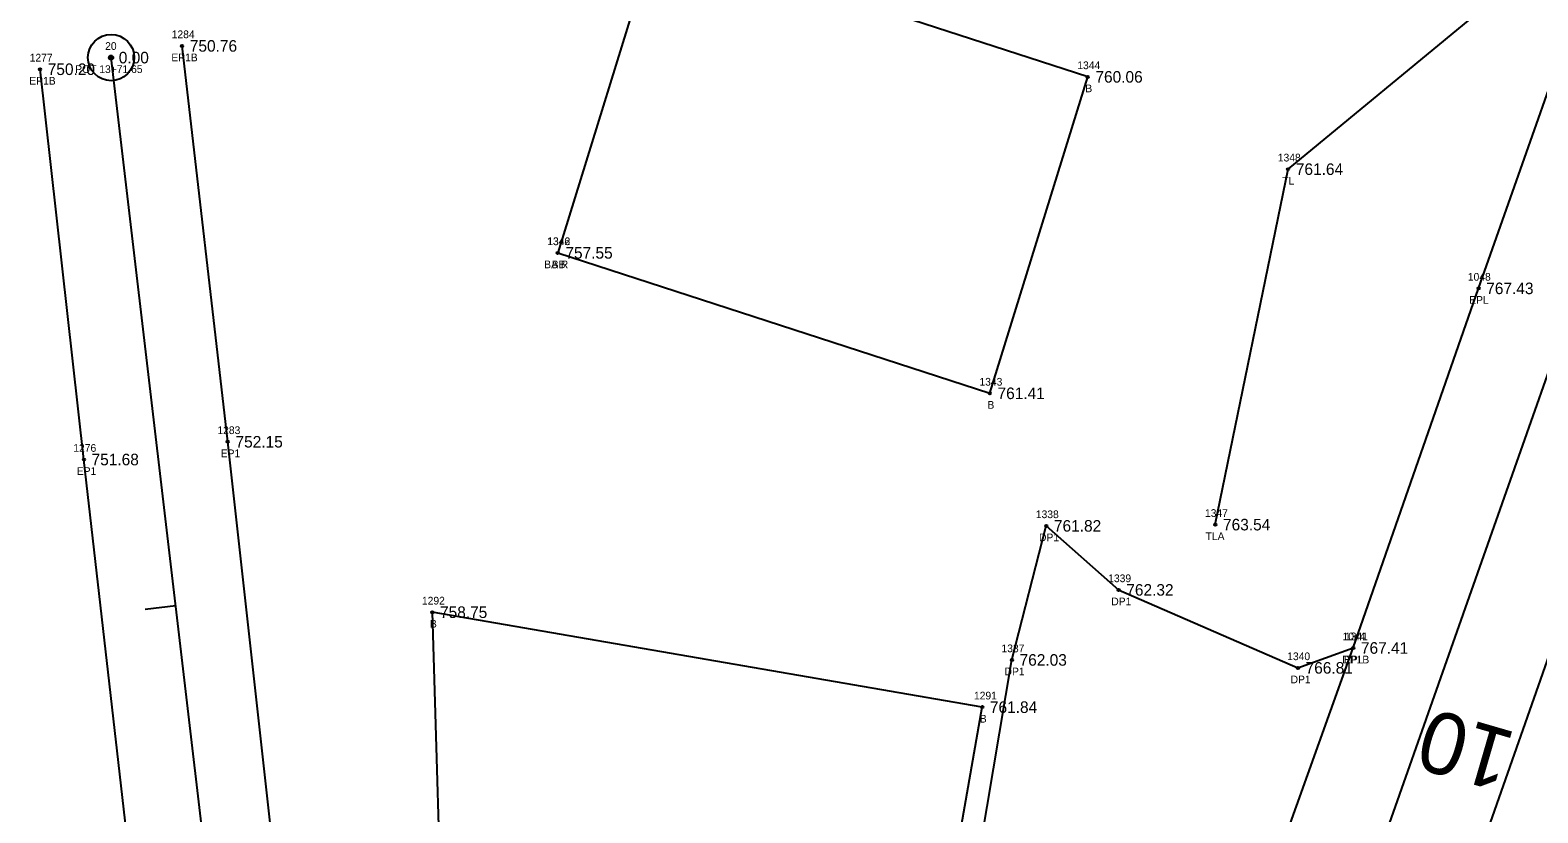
# Model space of a CAD drawing. Extents: x 1736563 to 1738032, y 1150548 to 1154248.
# Drawn here: x 1736805.9 to 1737001.6, y 1151446.2 to 1151547.8 of the extents above; entities that cross this region are included whole.
import ezdxf

# ---------------------------------------------------------------- set-up
doc = ezdxf.new("R2010")
doc.units = 0
for name, color, linetype in [('RD_EX_Bldg', 7, 'Continuous'), ('RD_EX_Bldg_txCode', 7, 'Continuous'), ('RD_EX_Driveway', 7, 'Continuous'), ('RD_EX_Driveway_txCode', 7, 'Continuous'), ('RD_EX_Road', 7, 'Continuous'), ('RD_EX_Road_txCode', 7, 'Continuous'), ('RD_EX_TX_Bldg_ELEV', 7, 'Continuous'), ('RD_EX_TX_Driveway_ELEV', 7, 'Continuous'), ('RD_EX_TX_Road_ELEV', 7, 'Continuous'), ('RD_EX_TX_VEG_ELEV', 7, 'Continuous'), ('RD_EX_VEG', 7, 'Continuous'), ('RD_EX_VEG_txCode', 7, 'Continuous'), ('RD_HC_Cl', 7, 'Continuous'), ('RD_HC_Data', 7, 'Continuous'), ('RD_HC_Data_Tic', 7, 'Continuous'), ('RD_HC_Survey_ELEV', 7, 'Continuous'), ('RD_HC_TX_Sta50', 7, 'Continuous'), ('RD_HC_txCode', 7, 'Continuous'), ('RD_SMD_Locator', 7, 'Continuous')]:
    doc.layers.add(name, color=color, linetype=linetype)

msp = doc.modelspace()

# ---------------------------------------------------------------- linework, layer by layer
at = {"layer": 'RD_EX_Bldg'}
for points in [[(1736874.36, 1151518.85), (1736930.44, 1151500.62), (1736943.14, 1151541.69), (1736887.06, 1151559.92), (1736874.36, 1151518.85)], [(1736863.77, 1151279.47), (1736867.06, 1151267.94), (1736888.13, 1151263.51), (1736915.64, 1151341.84), (1736909.15, 1151344.06), (1736920.76, 1151410.23), (1736929.45, 1151459.89), (1736858.09, 1151472.21), (1736863.77, 1151279.47)]]:
    msp.add_lwpolyline(points, dxfattribs=at)
at = {"layer": 'RD_EX_Driveway'}
msp.add_lwpolyline([(1736911.77, 1151279.81), (1736898.18, 1151283.49), (1736917.81, 1151341), (1736911.84, 1151344.33), (1736923.72, 1151409.18), (1736933.3, 1151466.02), (1736937.76, 1151483.42), (1736947.15, 1151475.11), (1736970.42, 1151464.99), (1736977.6, 1151467.57)], dxfattribs=at)
at = {"layer": 'RD_EX_Road'}
for points in [[(1736868.01, 1151157.6), (1736882.54, 1151196.52), (1736892.4, 1151226.58), (1736911.77, 1151279.81), (1736926.32, 1151321.94), (1736959.92, 1151418.27), (1736977.6, 1151467.57), (1736993.86, 1151514.24), (1737026.63, 1151607.21), (1737059.17, 1151698.64), (1737091.53, 1151790.84), (1737119.9, 1151870.3), (1737125.51, 1151887.21), (1737129.74, 1151897.31), (1737157.61, 1151979.19), (1737191.07, 1152073.18), (1737224.57, 1152167.62), (1737258.08, 1152262.33), (1737292.51, 1152359.5), (1737326.83, 1152457.35), (1737361.84, 1152556.63), (1737380.81, 1152611.37), (1737392.07, 1152607.38)], [(1736891.67, 1151150.12), (1736912.85, 1151210.27), (1736923.53, 1151240.29), (1736927.25, 1151250.75), (1736949.17, 1151313.27), (1736956.28, 1151332.78), (1736966.5, 1151361.77), (1736983.81, 1151412), (1736991.7, 1151434.32), (1737008.48, 1151482.13), (1737017.08, 1151506.24), (1737050.57, 1151600.07), (1737082.25, 1151690.44), (1737114.69, 1151782.27), (1737149.29, 1151879.88)], [(1736892.4, 1151226.58), (1736882.22, 1151227.11), (1736872.42, 1151233.52), (1736863.72, 1151257.25), (1736844.16, 1151381.05), (1736831.55, 1151494.33), (1736825.62, 1151545.71)], [(1736868.01, 1151157.6), (1736869.22, 1151173.32), (1736864.67, 1151193.4), (1736847.18, 1151224.87), (1736838.98, 1151250.85), (1736826.04, 1151376.69), (1736812.87, 1151492.03), (1736807.18, 1151542.68)]]:
    msp.add_lwpolyline(points, dxfattribs=at)
at = {"layer": 'RD_EX_VEG'}
msp.add_lwpolyline([(1736959.7, 1151483.58), (1736969.15, 1151529.71), (1736993.52, 1151549.78), (1737013.17, 1151613.01), (1737045.07, 1151703.49), (1737071.59, 1151800.28), (1737137.09, 1151986), (1737166.47, 1152079.74), (1737210.3, 1152172.1), (1737243.02, 1152268.91), (1737273.26, 1152365.06), (1737311.38, 1152461.44), (1737301.63, 1152483.31), (1737276.02, 1152508.8), (1737275.33, 1152531.71), (1737274.82, 1152550.06), (1737265.2, 1152579.56)], dxfattribs=at)
at = {"layer": 'RD_HC_Cl'}
for p, q in [((1736879.96, 1151154.46), (1737935.1, 1154148.31)), ((1736849.17, 1151266.7), (1736816.4, 1151544.19))]:
    msp.add_line(p, q, dxfattribs=at)
at = {"layer": 'RD_HC_Data'}
for radius in [3, 0.282]:
    msp.add_circle((1736816.4, 1151544.19), radius, dxfattribs=at)
at = {"layer": 'RD_HC_Data_Tic'}
msp.add_line((1736824.8, 1151473.04), (1736820.83, 1151472.57), dxfattribs=at)
at = {"layer": 'RD_SMD_Locator'}
for centre in [(1736825.62, 1151545.71), (1736816.4, 1151544.19), (1736807.18, 1151542.68), (1736943.14, 1151541.69), (1736969.15, 1151529.71), (1736874.36, 1151518.85), (1736874.36, 1151518.85), (1736993.86, 1151514.24), (1736930.44, 1151500.62), (1736831.55, 1151494.33), (1736812.87, 1151492.03), (1736937.76, 1151483.42), (1736959.7, 1151483.58), (1736947.15, 1151475.11), (1736858.09, 1151472.21), (1736977.6, 1151467.57), (1736977.6, 1151467.57), (1736933.3, 1151466.02), (1736970.42, 1151464.99), (1736929.45, 1151459.89)]:
    msp.add_circle(centre, 0.15, dxfattribs=at)

# ---------------------------------------------------------------- texts
at = {"layer": 'RD_EX_Bldg_txCode'}
for s, p in [('1344', (1736941.79, 1151542.69)), ('B', (1736942.83, 1151539.69)), ('1346', (1736872.99, 1151519.85)), ('1342', (1736873.02, 1151519.85)), ('BA R', (1736872.61, 1151516.85)), ('BB', (1736873.58, 1151516.85)), ('1343', (1736929.09, 1151501.62)), ('B', (1736930.13, 1151498.62)), ('1292', (1736856.74, 1151473.21)), ('B', (1736857.78, 1151470.21)), ('1291', (1736928.38, 1151460.89)), ('B', (1736929.14, 1151457.89))]:
    msp.add_text(s, height=1, dxfattribs=at).set_placement(p)
at = {"layer": 'RD_EX_Driveway_txCode'}
for s, p in [('1338', (1736936.41, 1151484.42)), ('DP1', (1736936.82, 1151481.42)), ('1339', (1736945.8, 1151476.11)), ('DP1', (1736946.2, 1151473.11)), ('1341', (1736976.53, 1151468.57)), ('1337', (1736931.95, 1151467.02)), ('1340', (1736969.03, 1151465.99)), ('DP1', (1736932.35, 1151464.02)), ('DP1B', (1736976.18, 1151465.57)), ('DP1', (1736969.47, 1151462.99))]:
    msp.add_text(s, height=1, dxfattribs=at).set_placement(p)
at = {"layer": 'RD_EX_Road_txCode'}
for s, p in [('1284', (1736824.27, 1151546.71)), ('1277', (1736805.84, 1151543.68)), ('EP1B', (1736824.22, 1151543.71)), ('EP1B', (1736805.79, 1151540.68)), ('1048', (1736992.47, 1151515.24)), ('EPL', (1736992.65, 1151512.24)), ('1283', (1736830.2, 1151495.33)), ('1276', (1736811.5, 1151493.03)), ('EP1', (1736830.63, 1151492.33)), ('EP1', (1736811.95, 1151490.03)), ('1044', (1736976.21, 1151468.57)), ('EPL', (1736976.39, 1151465.57))]:
    msp.add_text(s, height=1, dxfattribs=at).set_placement(p)
at = {"layer": 'RD_EX_TX_Bldg_ELEV'}
for s, p in [('760.06', (1736944.14, 1151540.94)), ('757.55', (1736875.36, 1151518.1)), ('757.55', (1736875.36, 1151518.1)), ('761.41', (1736931.44, 1151499.87)), ('758.75', (1736859.09, 1151471.46)), ('761.84', (1736930.45, 1151459.14))]:
    msp.add_text(s, height=1.5, dxfattribs=at).set_placement(p)
at = {"layer": 'RD_EX_TX_Driveway_ELEV'}
for s, p in [('761.82', (1736938.76, 1151482.67)), ('762.32', (1736948.15, 1151474.36)), ('767.41', (1736978.6, 1151466.82)), ('762.03', (1736934.3, 1151465.27)), ('766.81', (1736971.42, 1151464.24))]:
    msp.add_text(s, height=1.5, dxfattribs=at).set_placement(p)
at = {"layer": 'RD_EX_TX_Road_ELEV'}
for s, p in [('750.76', (1736826.62, 1151544.96)), ('750.20', (1736808.18, 1151541.93)), ('767.43', (1736994.86, 1151513.49)), ('752.15', (1736832.55, 1151493.58)), ('751.68', (1736813.87, 1151491.28)), ('767.41', (1736978.6, 1151466.82))]:
    msp.add_text(s, height=1.5, dxfattribs=at).set_placement(p)
at = {"layer": 'RD_EX_TX_VEG_ELEV'}
for s, p in [('761.64', (1736970.15, 1151528.96)), ('763.54', (1736960.7, 1151482.83))]:
    msp.add_text(s, height=1.5, dxfattribs=at).set_placement(p)
at = {"layer": 'RD_EX_VEG_txCode'}
for s, p in [('1348', (1736967.81, 1151530.71)), ('TL', (1736968.38, 1151527.71)), ('1347', (1736958.36, 1151484.58)), ('TLA', (1736958.44, 1151481.58))]:
    msp.add_text(s, height=1, dxfattribs=at).set_placement(p)
at = {"layer": 'RD_HC_Survey_ELEV'}
msp.add_text('0.00', height=1.5, dxfattribs=at).set_placement((1736817.4, 1151543.44))
at = {"layer": 'RD_HC_TX_Sta50'}
msp.add_text('10', height=8, rotation=163.8053, dxfattribs=at).set_placement((1736998.98, 1151456.5))
at = {"layer": 'RD_HC_txCode'}
for s, p in [('20', (1736815.63, 1151545.19)), ('POT 13+71.65', (1736811.75, 1151542.19))]:
    msp.add_text(s, height=1, dxfattribs=at).set_placement(p)

doc.saveas('drawing.dxf')
